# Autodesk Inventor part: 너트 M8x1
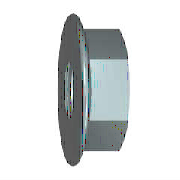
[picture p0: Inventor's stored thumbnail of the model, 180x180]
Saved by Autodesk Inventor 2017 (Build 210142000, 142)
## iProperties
Created: 2015-12
Part Number: 너트 M8x1
Material: 스테인리스강
Description: 플랜지붙이 6각 너트 - 일반 스레드
Document SubType Name: Modeling
Standard: ISO 4161
Designer: mdu
Standard Revision: 2판 1999-03-15
Standards Organization: ISO
Language: ko-KR
Size Designation: M8
Categories: <MemberInstance><Categories><Category DisplayName="조임쇠" InternalName="e4da775c-781d-43d5-af7c-5136215cf5a6" Mnemonic="FSTN"><Category DisplayName="너트" InternalN
Density: 8.08 g/cm^3
Appearance: 기본값
Mass: 9.03298 g
Surface Area: 8.90186 cm^2
Volume: 1.11794 cm^3
Author: mdu
IsCustomPart: 1
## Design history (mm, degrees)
sketch "스케치1"
  geometry: L1 (-1.844, 0)-(9.641, 0) reference; L2 (3.107, 6.5)-(2.288, 8.257); L3 (3.107, 6.5)-(8, 6.5); L4 (8, 6.5)-(8, 0); L5 (3.107, 6.5)-(3.107, 0); L6 (0, -1.835)-(0, 11.01) reference; A1 r 1.2 centre (1.2, 7.75) between (2.288, 8.257) and (0, 7.75); 1 further point
  constraints: 8 end point, 3 point on line, 2 perpendicular, 2 point on circle, 2 tangent, 1 centre point, 1 parallel
  dimensions: "d2" = 13 diameter of L3 L1 (= SW); "d4" = 17.9 dimension on A1 L1 (= LADI); "d5" = 1.2 radius of A1 (= PHH); "d15" = 8 distance between parallel lines of L4 L6 (= KOH); "d16" = 25 deg angle of L6 L2 (= KEWI)
revolve "링" sketch "스케치1" stored, may be unused: angle "d8" = 90 deg
sketch "스케치2"
  geometry: L1 (-6.5, -3.753)-(-6.5, 3.753); L2 (-6.5, 3.753)-(0, 7.506); L3 (0, 7.506)-(6.5, 3.753); L4 (6.5, 3.753)-(6.5, -3.753); L5 (6.5, -3.753)-(0, -7.506); L6 (0, -7.506)-(-6.5, -3.753); C1 r 4.9 at (0, 0); C2 r 7.75 at (0, 0) reference; 1 further point
  constraints: 12 end point, 1 centre point, 1 coincident, 1 vertical, 11 other
  dimensions: "d6" = 15.01111 distance of L5.end L2.end (= 1.1547 x SW)
extrude "본체" join sketch "스케치2" distance "d7" = 8 (= KOH); taper "d9" = 0 deg
sketch "스케치3"
  geometry: L1 (2.638, 7.506)-(8, 7.506) reference; L2 (8, 3.753)-(8, 7.506) reference; L3 (0, -7.75)-(0, 7.75) reference; L4 (-1.6, 0)-(9.6, 0) reference; L5 (7.419, 7.506)-(8, 6.5)
  constraints: 2 end point, 2 point on line
  dimensions: "d10" = 30 deg angle of L2 L5 (= ANG1); "d11" = 13 diameter of L5.end L4 (= SW0)
revolve "모따기1" sketch "스케치3" stored, may be unused: angle "d24" = 90 deg
sketch "스케치4"
  geometry: C1 r 7.75 at (0, 0) reference; 1 further point
  constraints: 1 coincident
hole "스레드" sketch "스케치4" at (0, 0) diameter "d25" = 6.647; stored, may be unused: countersink angle "d29" = 82 deg, drill point angle "d31" = 118 deg; dims "d26" = 6, "d27" = 4, "d28" = 2, "d30" = 8
workaxis "Work Axis1"
workplane "Work Plane1"
body "Solid1"
chamfer "모따기2" distance "d12" = 0.67658 (= -0.5 x GD1 + 0.5 x NND); stored, may be unused: angle "d13" = 30 deg, second distance "d46" = 0.67658 (= -0.5 x GD1 + 0.5 x NND)
chamfer "모따기3" distance "d51" = 0.67658 (= -0.5 x GD1 + 0.5 x NND); stored, may be unused: second distance "d52" = 2, angle "d53" = 45 deg
other parameters: "ANG1" = 30 deg [user parameter; used in 1 equation term], "KEWI" = 25 deg [user parameter; used in 1 equation term], "NND" = 8 [user parameter; used in 4 equation terms], "LADI" = 17.9 [user parameter; used in 2 equation terms], "SW" = 13 [user parameter; used in 3 equation terms], "PHH" = 1.2 [user parameter; used in 3 equation terms], "KOH" = 8 (= NND) [user parameter; used in 2 equation terms], "SW0" = 13 [user parameter; used in 1 equation term], "GD1" = 6.64684 (computed from THREADDIA, PTC, TOA) [user parameter; used in 3 equation terms], "d1" = 17.9 (= LADI), "d3" = 1.2 (= PHH), "d45" = 0, "d47" = 0, "d49" = 0, "d54" = 0, "GUL" = 0.67658 (= 0.541266 x PTC) [user parameter], "TPU" = 8 (computed from PTC) [user parameter], "RR" = 1.2 (= PHH) [user parameter], "THREADDIA" = 8 [user parameter; used in 1 equation term], "TOA" = 30 deg [user parameter; used in 1 equation term], "PTC" = 1.25 [user parameter; used in 4 equation terms], "GAL" = 0.67658 (= 0.541266 x PTC) [user parameter], "E0" = 15.015 (= 1.155 x SW) [user parameter]
